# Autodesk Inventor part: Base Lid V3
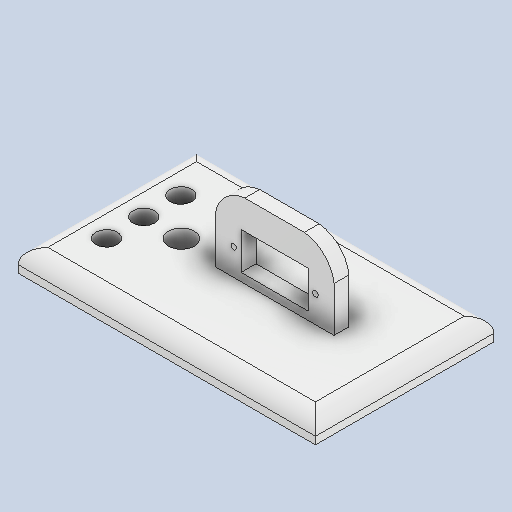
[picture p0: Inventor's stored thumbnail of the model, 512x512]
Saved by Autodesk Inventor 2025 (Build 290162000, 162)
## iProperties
Created: 2024-10
Part Number: Base Lid V3
Material: ABS Plastic
Document SubType Name: Modeling
Designer: Braidyn
Density: 1.06 g/cm^3
Appearance: Smooth - White
Author: Braidyn
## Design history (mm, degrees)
sketch "Sketch1"
  geometry: L1 (-50.8, 30.48)-(50.8, 30.48); L2 (50.8, 30.48)-(50.8, -30.48); L3 (50.8, -30.48)-(-50.8, -30.48); L4 (-50.8, -30.48)-(-50.8, 30.48); L5 (-50.8, 30.48)-(50.8, -30.48); L6 (50.8, 30.48)-(-50.8, -30.48); 1 further point
  constraints: 12 end point, 2 midpoint, 2 parallel, 1 horizontal, 1 perpendicular
  dimensions: "d0" = 101.6 distance of L2.end L3.end; "d1" = 60.96 distance of L1.end L2.end
extrude "Extrusion1" new body sketch "Sketch1" distance "d2" = 7.62; taper "d3" = 0 deg
sketch "Sketch3"
  geometry: L1 (0, 0)-(8.89, 0); L2 (-11.43, -2.54)-(29.21, -2.54); L3 (29.21, -2.54)-(29.21, 2.54); L4 (29.21, 2.54)-(-11.43, 2.54); L5 (-11.43, 2.54)-(-11.43, -2.54); L6 (-11.43, -2.54)-(29.21, 2.54); L7 (29.21, -2.54)-(-11.43, 2.54)
  constraints: 14 end point, 2 horizontal, 2 midpoint, 2 parallel, 1 perpendicular
  dimensions: "d14" = 8.89 distance of L1.start L1.end; "d15" = 40.64 distance of L4.end L3.end; "d16" = 5.08 distance of L3.end L2.end
extrude "Extrusion4" join sketch "Sketch3" distance "d17" = 25.4; taper "d18" = 0 deg
fillet "Fillet2" dims "d24" = 5.08
sketch "Sketch7"
  geometry: L1 (0, 25.4)-(40.64, 25.4) reference; L2 (0, 25.4)-(20.32, 25.4); L3 (20.32, 25.4)-(40.64, 25.4); L4 (0, 0)-(0, 25.4) reference; L5 (40.64, 0)-(40.64, 25.4) reference; A1 r 11.43 centre (11.352, 14.032) between (10.16, 25.4) and (0, 12.7); A2 r 11.43 centre (29.288, 14.032) between (40.64, 12.7) and (30.48, 25.4); 5 further points
  constraints: 5 midpoint, 4 end point, 4 point on circle, 2 centre point, 1 collinear
  dimensions: "d30" = 11.43 radius of A1; "d31" = 11.43 radius of A2
extrude "Extrusion7" cut sketch "Sketch7" distance "d32" = 101.6; taper "d33" = 0 deg
sketch "Sketch8"
  geometry: 1 further point
sketch "Sketch9"
  geometry: L1 (74.93, 0)-(-16.51, 0) reference; L2 (0, 0)-(40.64, 0) reference; L3 (-0.003, 0)-(40.64, 0); L4 (40.64, 0)-(20.319, 0); L5 (20.319, 0)-(20.319, 25.604); L6 (8.889, 2.778)-(31.749, 2.778); L7 (31.749, 2.778)-(31.749, 15.478); L8 (31.749, 15.478)-(8.889, 15.478); L9 (8.889, 15.478)-(8.889, 2.778); L10 (8.889, 2.778)-(31.749, 15.478); L11 (31.749, 2.778)-(8.889, 15.478); L12 (8.889, 9.128)-(3.809, 9.128); L13 (31.749, 9.128)-(36.829, 9.128); C1 r 0.953 at (6.349, 9.128); C2 r 0.953 at (34.289, 9.128); 2 further points
  constraints: 22 end point, 7 midpoint, 3 horizontal, 2 centre point, 2 parallel, 2 point on line, 1 collinear, 1 perpendicular, 1 vertical
  dimensions: "d34" = 22.86 distance of L8.end L7.end; "d35" = 12.7 distance of L7.end L6.end; "d36" = 5.08 distance of L12.start L12.end; "d37" = 5.08 distance of L13.start L13.end; "d38" = 1.905 diameter of C1; "d39" = 1.905 diameter of C2
extrude "Extrusion8" cut sketch "Sketch9" distance "d40" = 101.6; taper "d41" = 0 deg
sketch "Sketch11"
  geometry: L1 (-47.625, 27.305)-(47.625, 27.305); L2 (47.625, 27.305)-(47.625, -27.305); L3 (47.625, -27.305)-(-47.625, -27.305); L4 (-47.625, -27.305)-(-47.625, 27.305); L5 (-47.625, 27.305)-(47.625, -27.305); L6 (47.625, 27.305)-(-47.625, -27.305); 1 further point
  constraints: 12 end point, 2 midpoint, 2 parallel, 1 horizontal, 1 perpendicular
  dimensions: "d49" = 95.25 distance of L2.end L3.end; "d50" = 54.61 distance of L1.end L2.end
extrude "Extrusion10" join sketch "Sketch11" distance "d51" = 2.54; taper "d52" = 0 deg
sketch "Sketch10" dims "d44" = 7.366
  geometry: L1 (-45.72, -25.4)-(-45.72, 25.4) reference; L2 (-45.72, 0)-(-16.282, 0); L3 (-16.282, 0)-(-31.001, 0); L4 (-31.001, 0)-(-45.72, 0); L5 (-38.361, 0)-(-38.361, 25.4); L6 (-45.72, 25.4)-(45.72, 25.4) reference; L7 (-38.361, 0)-(-38.361, -25.4); L8 (-34.678, 0)-(-16.282, 0); C1 r 3.683 at (-38.361, 12.7); C2 r 3.683 at (-38.361, -12.7); C3 r 4.445 at (-25.48, 0); 2 further points
  constraints: 12 end point, 6 midpoint, 3 centre point, 3 point on line, 1 coincident, 1 collinear, 1 horizontal, 1 horizontal alignment, 1 perpendicular, 1 vertical, 2 other
  dimensions: "d43" = 7.366 diameter of C1; "d45" = 7.366 diameter of C2; "d48" = 8.89 diameter of C3
extrude "Extrusion9" cut sketch "Sketch10" distance "d46" = 101.6; taper "d47" = 0 deg
body "Solid1"
